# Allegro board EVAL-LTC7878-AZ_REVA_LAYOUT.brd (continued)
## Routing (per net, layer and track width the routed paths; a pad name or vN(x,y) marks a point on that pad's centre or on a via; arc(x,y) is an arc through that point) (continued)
UNNAMED_2_ADLTC7878_I88_VIN: length 3.5
  TOP w0.254: U1.2 73.02,90.91 72.01,91.92 C12.1
UNNAMED_2_ADLTC7878_I88_VOUT: length 27.7
  TOP w0.254: U1.25 77.95,92.43 78.74,93.22 78.74,93.73 v3(79.38,94.36) 79.95,94.36 R71.1 ; TP12.1 v4(59.31,88.65)
  LAYER_3 w0.254: v4(59.31,88.65) 64.14,88.65 65.41,89.92 68.58,89.92 69.85,88.65 72.01,88.65 75.06,91.69 76.58,91.69 79.25,94.36 v3(79.38,94.36)
UNNAMED_2_CAP_I49_N1: length 3.6
  TOP w0.254: U1.29 75.95,92.93 75.44,93.45 75.44,94.36 v4(75.18,94.61) 75.18,94.94 C17.1
  BOTTOM w0.254: v4(75.18,94.61) 75.18,94.94 C17.1
UNNAMED_2_CAP_I49_N2: length 6.1
  TOP w0.254: 76.28,94.98 C18.1 76.45,93.68 U1.28 ; 76.28,94.98 76.38,94.87 v4(76.71,94.87) ; 76.28,94.98 C17.2 76.26,96.03 R19.2 R13.2
  BOTTOM w0.254: C17.2 76.38,94.87 v4(76.71,94.87)
UNNAMED_2_CAP_I57_N1: length 1
  TOP w0.254: R12.2 C15.1
UNNAMED_2_CAP_I58_N1: length 1.9
  TOP w0.254: U1.31 74.95,92.55 74.17,93.33 74.17,93.54 C16.1
UNNAMED_2_CAP_I59_N2: length 2.6
  TOP w0.254: C19.2 73.48,85.29 74.95,86.76 U1.10
UNNAMED_2_CAP_I188_N1: length 26.9
  TOP w0.254: v3(80.52,95.5) 80.45,95.43 R71.2 ; R33.1 108.16,105.84 109.29,105.84 109.47,105.66 109.47,101.85 109.22,101.6 R31.2
  LAYER_5 w0.254: v3(98.3,101.6) 94.87,101.6 91.19,97.92 82.3,97.92 80.52,96.14 v3(80.52,95.5)
  vias: v1(96.14,108.71) v1(96.14,107.44) v1(96.14,106.17) v1(96.14,104.9) v1(97.41,108.71) v1(97.41,107.44) v1(97.41,106.17) v1(97.41,104.9) v1(98.68,108.71) v1(98.68,107.44) v1(98.68,106.17) v1(98.68,104.9) v1(99.95,108.71) v1(99.95,107.44) v1(99.95,106.17) v1(99.95,104.9) v3(95,103.76) v3(95.5,103.76) v3(96.01,103.76) v3(97.79,103.76) v3(98.3,103.76) v3(98.81,103.76) v3(101.09,103.76) v3(101.6,103.76) v3(102.11,103.76) v3(104.01,113.79) v3(104.01,112.27) v3(104.01,110.74) v3(104.39,103.76) v3(104.9,103.76) v3(105.41,103.76) v3(106.81,113.79) v3(106.81,112.27) v3(106.81,110.74)
UNNAMED_2_IND_I44_N1: length 38.5
  TOP w0.254: v3(74.04,107.44) 74.02,107.47 L1.1 ; R16.1 v3(77.47,97.92) ; R14.2 v3(63.5,105.28) ; R19.1 v3(76.2,97.79)
  LAYER_5 w0.254: v3(63.5,105.28) 63.12,104.9 63.12,100.08 63.88,99.31 73.79,99.31 75.18,97.92 75.18,97.54 75.82,96.9 76.83,96.9 77.47,97.54 v3(77.47,97.92) ; v3(76.2,97.79) 76.2,98.3 77.22,99.31 77.22,99.82 75.95,101.09 75.95,105.54 v3(74.04,107.44)
  vias: v2(70.36,104.39) v2(70.36,103.63) v2(71.12,104.39) v2(71.12,103.63) v2(71.88,104.39) v2(71.88,103.63) v2(72.64,104.39) v2(72.64,103.63) v2(73.41,104.39) v2(73.41,103.63)
UNNAMED_2_NCTESTPAD_I129_N1: length 5.2
  TOP w0.254: R34.2 R35.1
  TOP w0.381: R34.2 83.44,85.67 83.44,85.03 85.09,83.38 TP20.1
UNNAMED_2_RES_I34_N1: length 7.8
  TOP w0.254: v3(52.83,103.25) 52.83,103.61 M2.4
  LAYER_5 w0.508: v3(52.83,108.84) v3(52.83,103.25)
  BOTTOM w0.254: M6.4 52.29,108.3 v3(52.83,108.84)
UNNAMED_2_RES_I154_N1: length 7.7
  TOP w0.254: v3(58.93,110.49) 58.54,110.1 M1.4
  LAYER_5 w0.508: v3(53.34,110.49) v3(58.93,110.49)
  BOTTOM w0.254: M5.4 53.73,110.1 v3(53.34,110.49)
UNNAMED_2_TRANNMOSFET8P_I163_G: length 7.9
  TOP w0.254: v3(92.96,102.62) 92.67,102.91 M3.4
  LAYER_5 w0.508: v3(87.25,102.62) v3(92.96,102.62)
  BOTTOM w0.254: v3(87.25,102.62) 87.54,102.91 M7.4
UNNAMED_2_TRANNMOSFET8P_I168_G: length 8.2
  TOP w0.254: M4.4 94.12,104.55 93.73,104.15 v3(93.73,104.01)
  LAYER_5 w0.508: v3(93.73,109.86) v3(93.73,104.01)
  BOTTOM w0.254: M8.4 94.12,109.46 v3(93.73,109.86)
VFB_1: length 21.8
  TOP w0.254: v4(80.45,84.84) R36.1 R35.2 80.26,85.85 79.5,86.61 78.23,86.61 77.95,86.9 U1.16
  TOP w0.381: R5.1 TP18.1 v4(86.49,75.31)
  LAYER_5 w0.254: v4(80.45,84.84) 86.49,78.8 v4(86.49,75.31)
VFB_2: length 109.5
  TOP w0.254: U2.16 77.95,20.92 78.36,20.51 79.57,20.51 80.26,19.81 R65.2 R66.1 v4(80.45,18.8) ; TP43.1 v4(86.49,9.27)
  TOP w0.381: R5.2 v4(86.49,69.22)
  LAYER_4 w0.254: v4(86.49,9.27) 94.23,9.27 111.25,26.29 111.25,54.99 98.17,68.07 87.63,68.07 v4(86.49,69.22)
  LAYER_5 w0.254: v4(86.49,9.27) 86.49,12.76 v4(80.45,18.8)
VOUT: length 101.2
  TOP w0.254: TP19.1 v3(88.77,82.04) ; R32.2 110.24,101.56 109.98,101.81 109.98,105.66 110.14,105.82 R33.2 ; R63.2 110.14,39.78 109.98,39.62 109.98,35.77 R62.2
  TOP w0.381: R34.1 84.96,85.85 TP19.1 ; v3(88.77,16) TP44.1 84.96,19.81 R64.1
  LAYER_2 w0.381: v2(114.3,103.5) 114.3,95.63 100.71,82.04 v3(88.77,82.04) ; v3(88.77,16) 100.58,16 114.3,29.72 v2(114.3,37.47)
  vias: v2(114.3,108.58) v2(114.3,107.31) v2(114.3,106.05) v2(114.3,104.78) v2(114.3,42.55) v2(114.3,41.27) v2(114.3,40.01) v2(114.3,38.73) v2(115.19,108.58) v2(115.19,107.31) v2(115.19,106.05) v2(115.19,104.78) v2(115.19,103.5) v2(115.19,42.55) v2(115.19,41.27) v2(115.19,40.01) v2(115.19,38.73) v2(115.19,37.47) v3(115.44,113.92) v3(115.44,112.39) v3(115.44,110.87) v3(115.44,47.88) v3(115.44,46.35) v3(115.44,44.83) v3(118.24,113.92) v3(118.24,112.39) v3(118.24,110.87) v3(118.24,47.88) v3(118.24,46.35) v3(118.24,44.83)

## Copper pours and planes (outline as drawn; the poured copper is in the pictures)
SGND1 on LAYER_4 (solid shape): 74.04,87.63 72.96,87.63 72.71,87.38 72.39,87.38 72.39,87.69 72.83,88.14 74.04,88.14
SGND1 on TOP: 83.06,89.28 83.06,88.52 82.42,88.52 82.42,86.49 81.66,86.49 81.66,89.28
SGND1 on TOP: 79.12,82.55 78.36,82.55 78.36,84.45 79.12,84.45
SGND1 on TOP: 81.66,85.22 82.93,85.22 82.93,84.45 82.42,84.45 82.42,81.92 81.66,81.92
SGND1 on TOP: 83.06,91.31 83.06,90.55 81.66,90.55 81.66,91.31
SGND1 on TOP: 69.6,85.85 69.6,84.96 71.37,84.96 71.37,85.85
SGND1 on TOP: 80.99,82.55 82.84,82.55
SGND1 on BOTTOM: 68.58,92.08 68.58,82.04 83.82,82.04 83.82,92.08
SGND1 on LAYER_2: 38.1,135.79 39.27,134.62 39.26,134.49 39.24,134.37 39.24,101.35 57.53,83.06 67.82,83.06 68.58,83.82 68.58,88.9 69.98,88.9 69.98,92.08 83.82,92.08 83.82,81.92 69.72,81.92 68.58,80.77 56.64,80.77 36.96,100.46 36.96,134.37 36.94,134.49 36.93,134.62
SGND1 on LAYER_4: 79.38,87.63 73.41,87.63 73.41,91.82 79.38,91.82
SGND1 on LAYER_5: 73.41,91.82 73.41,88.52 74.8,88.52 75.56,87.76 79.38,87.76 79.38,91.82
SGND2 on TOP: 78.36,18.36 78.37,18.4 78.41,18.41 79.07,18.41 79.11,18.4 79.12,18.36 79.12,16.56 79.11,16.53 79.07,16.51 78.41,16.51 78.37,16.53 78.36,16.56
SGND2 on BOTTOM: 68.71,26.16 68.71,16.51 83.95,16.51 83.95,26.16
SGND2 on LAYER_2: 69.98,26.16 83.95,26.16 83.95,16.51 71.88,16.51 69.09,13.72 48.39,13.72 39.02,4.35 39.02,4.35 38.61,4.03 38.1,3.91 37.27,4.25 36.93,5.08 37.04,5.57 37.34,5.97 47.37,16 67.44,16 68.71,17.27 68.71,22.73 69.98,22.73
SGND2 on LAYER_4: 73.15,25.65 73.15,21.59 79.25,21.59 79.25,25.65
SGND2 on LAYER_5: 73.15,25.65 73.15,22.48 74.93,22.48 75.82,21.59 79.25,21.59 79.25,25.65
VIN on TOP: 2.79,129.79 58.8,129.79 58.8,111.25 18.92,111.25 18.41,110.74 18.41,81.28 36.2,63.5 58.93,63.5 58.93,45.09 16.51,45.09 16.26,45.34 16.26,60.58 2.54,74.3 2.54,129.54
VIN on BOTTOM: 2.92,129.79 58.93,129.79 58.93,111.12 18.92,111.12 18.41,110.62 18.41,81.28 36.2,63.5 58.93,63.5 58.93,45.09 16.51,45.09 16.26,45.34 16.26,60.58 2.54,74.3 2.54,129.41
DRVCC_1 on TOP: 70.61,94.36 69.22,94.36 69.22,95.38 70.61,95.38
DRVCC_1 on TOP: 57.62,92.46 59.47,92.46
DRVCC_1 on TOP: 70.48,90.74 70.48,90.11 71.95,90.11 72.14,90.3 72.14,90.49 71.88,90.74
DRVCC_2 on TOP: 70.74,28.19 69.22,28.19 69.22,29.34 70.74,29.34
GROUND on TOP (solid shape): 74.93,87.96 74.49,87.96 74.18,88.27 72.78,88.27 72.78,88.47 72.87,88.56 74.18,88.56 74.5,88.87 74.93,88.87
GROUND on TOP (solid shape): 74.93,21.92 74.5,21.92 74.19,22.23 72.81,22.22 72.81,22.4 72.92,22.52 74.19,22.52 74.5,22.82 74.93,22.82
GROUND on TOP, BOTTOM: 1.27,138.43 151.13,138.43 151.13,1.27 1.27,1.27
GROUND on LAYER_2: 1.27,138.43 151.13,138.43 151.13,1.27 1.27,1.27
GROUND on LAYER_3, LAYER_4: 1.27,1.27 1.27,138.43 151.13,138.43 151.13,1.27
GROUND on LAYER_5: 1.27,138.43 1.27,1.27 151.13,1.27 151.13,138.43 ; 1 cut-out
INTVCC_1 on TOP: 76.07,83.57 74.93,83.57 74.93,84.45 76.07,84.45
INTVCC_1 on TOP: 57.5,83.82 59.34,83.82
INTVCC_1 on TOP: 84.84,88.27 84.84,86.55 83.95,86.55 83.95,88.27
ITH_1 on TOP: 79.85,74.68 81.7,74.68
ITH_1 on TOP: 78.11,82.55 77.34,82.55 77.34,84.45 78.11,84.45
ITH_2 on TOP: 79.85,8.64 81.7,8.64
RUN_1 on TOP: 67.06,87 67.06,86.11 71.37,86.11 71.37,87
RUN_2 on TOP: 67.69,20.95 67.69,20.07 71.37,20.07 71.37,20.95
SS_1 on TOP: 74.13,74.68 75.98,74.68
SS_2 on TOP: 74.13,8.64 75.98,8.64
SYNC_2 on TOP: 83.06,90.3 83.06,89.53 81.66,89.53 81.66,90.3
UNNAMED_1_ADLTC7878_I123_BG1 on TOP: 51.82,35.94 51.82,34.67 52.83,34.67 52.83,35.94
UNNAMED_1_ADLTC7878_I123_BOOST1 on TOP: 71.88,29.34 72.83,29.34 72.83,28.57 73.47,27.94 74.42,27.94 74.42,26.92 73.41,26.92 71.88,28.45
UNNAMED_1_ADLTC7878_I123_BOOST2 on TOP: 73.79,19.56 73.79,18.03 74.04,18.03 74.04,17.32 74.03,17.29 73.99,17.27 73.08,17.27 73.04,17.29 73.03,17.32 73.03,19.56
UNNAMED_1_ADLTC7878_I123_CSN on TOP: 109.6,32.64 109.6,30.1 107.95,30.1 107.95,32.64
UNNAMED_1_ADLTC7878_I123_CSP on TOP: 109.6,34.8 109.6,32.89 107.19,32.89 107.19,34.8
UNNAMED_1_ADLTC7878_I123_EXTVCC on TOP: 71.38,23.75 71.95,23.75 71.95,23.63 71.4,23.07 71.33,22.99 71.29,22.91 71.28,22.9 71.26,22.87 71.25,22.86 71.25,22.84 71.25,22.71 71.25,22.29 69.85,22.29 69.85,23.67 69.86,23.71 69.9,23.72 71.24,23.72 71.31,23.73
UNNAMED_1_ADLTC7878_I123_FREQ on TOP: 80.26,23.19 80.28,23.23 80.31,23.24 81.36,23.24 81.39,23.23 81.41,23.19 81.41,22.53 81.39,22.49 81.36,22.48 80.31,22.48 80.28,22.49 80.26,22.53
UNNAMED_1_ADLTC7878_I123_ISNSD on TOP: 75.69,29.34 75.69,28.07 75.31,28.07 74.8,28.57 74.8,29.34
UNNAMED_1_ADLTC7878_I123_ISNSD on BOTTOM: 74.8,29.34 74.8,27.56 75.69,27.56 75.69,29.34
UNNAMED_1_ADLTC7878_I123_ISNSN on TOP: 77.28,27.43 77.28,29.02 77.15,29.15 77.15,30.1 79.38,30.1 79.38,29.02 78.49,29.02 78.49,27.43 78.36,27.3 77.41,27.3
UNNAMED_1_ADLTC7878_I123_ISNSN on BOTTOM: 77.72,28.32 75.95,28.32 75.95,27.56 77.72,27.56
UNNAMED_1_ADLTC7878_I123_ISNSP on TOP: 74.93,30.48 74.93,29.59 75.95,29.59 75.95,27.3 77.03,27.3 77.03,28.89 76.83,29.08 76.83,30.48
UNNAMED_1_ADLTC7878_I123_ITHB on TOP: 77.34,19.76 77.36,19.8 77.39,19.81 77.67,19.81 77.69,19.81 77.71,19.8 78.09,19.41 78.1,19.4 78.11,19.38 78.11,18.72 78.09,18.68 78.05,18.67 77.39,18.67 77.36,18.68 77.34,18.72
UNNAMED_1_ADLTC7878_I123_PGOOD on TOP: 68.42,8.64 70.27,8.64
UNNAMED_1_ADLTC7878_I123_SW1 on TOP: 62.48,34.67 62.48,43.56 59.56,43.56 59.05,43.05 57.28,43.05 57.28,44.83 53.34,44.83 53.34,34.67
UNNAMED_1_ADLTC7878_I123_SW1 on TOP: 74.42,29.21 74.42,28.32 73.53,28.32 73.15,28.7 73.15,29.21
UNNAMED_1_ADLTC7878_I123_SW1 on BOTTOM: 62.48,43.56 62.48,34.67 53.47,34.67 53.47,43.05 54.99,43.05 54.99,44.83 58.55,44.83 59.82,43.56
UNNAMED_1_ADLTC7878_I123_SW2 on TOP: 76.96,46.23 76.96,34.67 85.6,34.67 85.6,37.97 92.84,37.97 92.84,39.5 94.87,39.5 94.87,43.18 92.84,43.18 92.84,46.23
UNNAMED_1_ADLTC7878_I123_SW2 on TOP: 75.06,19.81 75.06,18.41 74.17,18.41 74.17,19.3 74.68,19.81
UNNAMED_1_ADLTC7878_I123_SW2 on TOP: 79.25,30.61 79.25,32.13 78.49,32.13 78.49,30.61
UNNAMED_1_ADLTC7878_I123_SW2 on BOTTOM: 77.09,46.23 77.09,34.67 86.61,34.67 86.61,37.97 92.96,37.97 93.34,38.35 95,38.35 95,42.04 92.96,42.04 92.96,46.23
UNNAMED_1_ADLTC7878_I123_VIN on TOP: 70.74,27.81 70.74,27.43 72.27,25.9 72.28,25.88 72.45,25.59 72.74,25.42 72.76,25.41 72.94,25.23 72.98,25.13 73.04,25.04 73.05,25.03 73.05,25 73,24.91 72.98,24.89 72.96,24.88 72.3,24.88 72.28,24.88 72.26,24.9 72.02,25.13 72.01,25.14 71.99,25.15 70.03,25.15 69.99,25.16 69.98,25.2 69.98,27.81
UNNAMED_1_ADLTC7878_I123_VOUT on TOP: 61.34,23.05 61.34,22.1 58.42,22.1 58.42,23.05
UNNAMED_1_ADLTC7878_I123_VOUT on TOP: 57.62,22.61 59.47,22.61
UNNAMED_1_ADLTC7878_I123_VOUT on TOP: 80.45,27.94 80.45,28.7 79.06,28.7 79.06,27.94
UNNAMED_1_CAP_I88_N2 on TOP: 109.86,34.8 110.74,34.8 110.74,32.64 111.51,32.64 111.51,30.1 109.86,30.1
UNNAMED_1_CAP_I107_N1 on TOP: 80.84,29.02 80.84,30.04 79.69,30.04 79.69,29.02
UNNAMED_1_CAP_I107_N1 on TOP: 95.25,49.4 95.25,38.48 94.11,37.34 93.34,37.34 93.34,35.56 93.73,35.18 108.46,35.18 108.46,36.2 109.09,36.2 109.09,40.13 109.47,40.13 109.47,49.4
UNNAMED_1_CAP_I107_N1 on BOTTOM: 95.25,49.53 95.25,38.61 94.36,37.72 93.34,37.72 93.34,35.81 93.85,35.31 108.97,35.31 108.97,49.53
UNNAMED_1_IND_I80_N1 on TOP: 77.98,30.61 77.98,32.13 77.22,32.13 77.22,30.61
UNNAMED_1_IND_I80_N1 on TOP: 63.25,46.23 63.25,34.67 75.44,34.67 75.44,46.23
UNNAMED_1_IND_I80_N1 on BOTTOM: 63.25,46.23 63.25,34.67 75.06,34.67 75.06,46.23
UNNAMED_1_RES_I60_N1 on TOP: 57.66,44.83 57.66,43.43 58.93,43.43 59.44,43.94 59.94,43.94 59.94,44.83
UNNAMED_1_RES_I60_N1 on BOTTOM: 54.61,44.83 54.61,43.43 53.09,43.43 53.09,44.83
UNNAMED_1_RES_I61_N1 on TOP: 51.69,36.2 53.09,36.2 53.09,38.48 51.69,38.48
UNNAMED_1_RES_I61_N1 on BOTTOM: 52.7,43.05 52.07,42.42 51.69,42.42 51.69,41.53 53.09,41.53 53.09,43.05
UNNAMED_1_RES_I75_N1 on TOP: 86.11,37.47 86.11,36.2 87.5,36.2 87.5,37.47
UNNAMED_1_RES_I75_N1 on TOP: 91.57,36.2 93.09,36.2 93.09,37.21 92.84,37.47 91.57,37.47
UNNAMED_1_RES_I75_N1 on BOTTOM: 88.65,37.47 88.65,36.2 87,36.2 87,37.47
UNNAMED_1_RES_I102_N1 on TOP: 93.47,39.24 93.47,37.72 93.98,37.72 94.87,38.61 94.87,39.24
UNNAMED_1_RES_I102_N1 on BOTTOM: 94.74,42.42 94.74,43.69 94.36,43.69 93.98,44.07 93.47,44.07 93.47,42.42
UNNAMED_2_ADLTC7878_I88_BG1 on TOP: 51.82,101.98 51.82,100.71 52.83,100.71 52.83,101.98
UNNAMED_2_ADLTC7878_I88_CSN on TOP: 109.6,98.68 109.6,96.14 107.95,96.14 107.95,98.68
UNNAMED_2_ADLTC7878_I88_CSP on TOP: 109.6,100.71 109.6,98.93 107.19,98.93 107.19,100.71
UNNAMED_2_ADLTC7878_I88_EXTVCC on TOP: 69.85,88.27 69.85,89.79 71.88,89.79 71.88,89.53 71.25,88.9 71.25,88.27
UNNAMED_2_ADLTC7878_I88_ISNSN on TOP: 77.15,93.6 77.15,95.06 76.96,95.25 76.96,96.14 79.25,96.14 79.25,95.12 78.36,95.12 78.36,93.47 78.23,93.34 77.41,93.34
UNNAMED_2_ADLTC7878_I88_ISNSN on BOTTOM: 75.82,94.36 75.82,93.6 77.53,93.6 77.53,94.36
UNNAMED_2_ADLTC7878_I88_PGOOD on TOP: 68.42,74.68 70.27,74.68
UNNAMED_2_ADLTC7878_I88_SW1 on TOP: 62.48,100.71 62.48,109.6 59.56,109.6 59.05,109.09 57.28,109.09 57.28,110.87 53.34,110.87 53.34,100.71
UNNAMED_2_ADLTC7878_I88_SW1 on TOP: 73.15,95.25 74.55,95.25 74.55,94.23 73.66,94.23 73.15,94.74
UNNAMED_2_ADLTC7878_I88_SW1 on TOP: 74.3,97.03 74.3,97.66 75.5,97.66 75.5,96.77 74.55,96.77
UNNAMED_2_ADLTC7878_I88_SW1 on BOTTOM: 62.48,109.6 62.48,100.71 53.47,100.71 53.47,109.09 54.99,109.09 54.99,110.87 58.55,110.87 59.82,109.6
UNNAMED_2_ADLTC7878_I88_SW2 on TOP: 77.09,112.27 77.09,100.71 85.72,100.71 85.72,104.01 92.96,104.01 92.96,105.54 95,105.54 95,109.22 92.96,109.22 92.96,112.27
UNNAMED_2_ADLTC7878_I88_SW2 on TOP: 74.17,85.85 75.06,85.85 75.06,84.45 74.17,84.45
UNNAMED_2_ADLTC7878_I88_SW2 on TOP: 78.36,96.65 78.36,98.17 79.12,98.17 79.12,96.65
UNNAMED_2_ADLTC7878_I88_SW2 on BOTTOM: 77.09,112.27 77.09,100.71 86.61,100.71 86.61,104.01 92.96,104.01 93.34,104.39 95,104.39 95,108.08 92.96,108.08 92.96,112.27
UNNAMED_2_ADLTC7878_I88_VIN on TOP: 69.98,93.85 69.98,91.19 72.01,91.19 72.39,90.81 73.53,90.81 73.53,91.19 73.03,91.19 70.74,93.47 70.74,93.85
UNNAMED_2_ADLTC7878_I88_VOUT on TOP: 61.47,89.03 61.47,88.01 58.29,88.01 58.29,89.03
UNNAMED_2_ADLTC7878_I88_VOUT on TOP: 57.62,88.65 59.47,88.65
UNNAMED_2_ADLTC7878_I88_VOUT on TOP: 80.39,94.74 80.39,93.85 78.87,93.85 78.87,94.74
UNNAMED_2_CAP_I49_N1 on BOTTOM: 74.68,95.38 74.68,93.6 75.56,93.6 75.56,95.38
UNNAMED_2_CAP_I49_N2 on TOP: 75.82,93.34 75.82,95.63 74.8,95.63 74.8,96.52 76.71,96.52 76.71,95.12 76.9,94.93 76.9,93.34
UNNAMED_2_CAP_I57_N1 on TOP: 79.12,82.3 79.12,81.41 77.34,81.41 77.34,82.3
UNNAMED_2_CAP_I58_N1 on TOP: 71.88,95.38 72.83,95.38 72.83,94.55 73.41,93.98 74.42,93.98 74.42,93.09 73.28,93.09 71.88,94.49
UNNAMED_2_CAP_I59_N2 on TOP: 73.03,85.6 73.03,83.31 74.04,83.31 74.04,84.07 73.91,84.2 73.91,85.6
UNNAMED_2_CAP_I132_N2 on TOP: 109.86,100.71 110.74,100.71 110.74,98.68 111.51,98.68 111.51,96.14 109.86,96.14
UNNAMED_2_CAP_I188_N1 on TOP: 79.63,95.89 79.63,95 80.77,95 80.77,95.89
UNNAMED_2_CAP_I188_N1 on TOP: 95.38,115.57 95.38,104.65 94.23,103.5 93.47,103.5 93.47,101.73 93.85,101.35 108.58,101.35 108.58,102.23 109.09,102.23 109.09,106.3 109.47,106.3 109.47,115.57
UNNAMED_2_CAP_I188_N1 on BOTTOM: 95.38,115.57 95.38,104.65 94.49,103.76 93.47,103.76 93.47,101.85 93.98,101.35 109.09,101.35 109.09,115.57
UNNAMED_2_IND_I44_N1 on TOP: 77.09,96.65 77.09,98.17 77.85,98.17 77.85,96.65
UNNAMED_2_IND_I44_N1 on TOP, BOTTOM: 63.25,112.27 63.25,100.71 75.44,100.71 75.44,112.27
UNNAMED_2_NCTESTPAD_I129_N1 on TOP: 84.17,82.55 86.01,82.55
UNNAMED_2_NCTESTPAD_I129_N1 on TOP: 83.63,86.23 83.63,85.47 81.66,85.47 81.66,86.23
UNNAMED_2_RES_I34_N1 on TOP: 51.69,102.23 53.09,102.23 53.09,104.52 51.69,104.52
UNNAMED_2_RES_I34_N1 on BOTTOM: 52.7,109.09 52.07,108.46 51.69,108.46 51.69,107.57 53.09,107.57 53.09,109.09
UNNAMED_2_RES_I154_N1 on TOP: 57.66,110.87 57.66,109.47 58.93,109.47 59.44,109.98 59.94,109.98 59.94,110.87
UNNAMED_2_RES_I154_N1 on BOTTOM: 54.61,110.87 54.61,109.47 53.09,109.47 53.09,110.87
UNNAMED_2_TRANNMOSFET8P_I163_G on TOP: 91.69,102.36 93.22,102.36 93.22,103.38 92.96,103.63 91.69,103.63
UNNAMED_2_TRANNMOSFET8P_I163_G on TOP: 86.11,103.5 86.11,102.23 87.5,102.23 87.5,103.5
UNNAMED_2_TRANNMOSFET8P_I163_G on BOTTOM: 88.65,103.5 88.65,102.23 87,102.23 87,103.5
UNNAMED_2_TRANNMOSFET8P_I168_G on TOP: 93.47,105.28 93.47,103.76 93.98,103.76 94.87,104.65 94.87,105.28
UNNAMED_2_TRANNMOSFET8P_I168_G on BOTTOM: 94.87,108.46 94.87,109.86 94.23,109.86 93.98,110.11 93.47,110.11 93.47,108.46
VFB_1 on TOP: 81.41,86.23 81.41,84.45 80.26,84.45 80.26,85.98 80.52,86.23
VFB_1 on TOP: 85.56,74.68 87.41,74.68
VFB_2 on TOP: 85.56,8.64 87.41,8.64
VOUT on TOP: 87.29,82.55 89.24,82.55
VOUT on TOP: 109.98,115.57 135.89,115.57 135.89,93.98 149.86,93.98 149.86,67.31 135.89,67.31 135.89,36.2 110.36,36.2 110.36,40.13 109.98,40.13 109.98,49.4 121.28,49.4 121.28,102.23 110.36,102.23 110.36,106.3 109.98,106.3
VOUT on BOTTOM: 113.03,115.57 135.89,115.57 135.89,93.98 149.86,93.98 149.86,67.31 135.89,67.31 135.89,36.2 112.39,36.2 112.39,49.4 121.28,49.4 121.28,102.23 113.03,102.23

Small or netless copper shapes (teardrops, artwork), in the pictures only: 87 on TOP, 2 on BOTTOM, 2 on LAYER_2, 2 on LAYER_3, 6 on LAYER_4, 41 on LAYER_5

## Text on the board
Ref Des/Silkscreen Top: 70V PARALLEL DUAL PHASE | 4-SWITCH BUCK-BOOST | EVAL-LTC7878-AZ | LTC7878
DIMENSION: FAB NOTES REVISION: 2ND NOVEMBER 2022 | 8.   IMPEDANCE REQUIREMENTS: IF NO STACKUP IS DEFINED, THE VENDOR IS ALLOWED TO ADJUST THE DIELECTRIC | 13.  PLATING SPECIFICATION: | 9.   FILLET OPTIONS TO ENHANCE RELIABILITY AT PAD JUNCTIONS WHERE SPACING PERMITS. | 10.  THIEVING: | 11.  LAYER TO LAYER REGISTRATION SHALL BE WITHIN 0.003 INCHES. | 12.  DRILL SIZES ARE FINISHED HOLE SIZES. ALL HOLES SHALL BE LOCATED WITHIN 0.005 INCHES DTP,UNLESS SPECIFIED. | 14.  SURFACE FINISH: | 15.  SOLDERMASK: | 1.   DIMENSIONS ARE IN INCHES (EXCEPT WHERE NOTED). | ALL DOCUMENTS & SPECIFICATIONS REFERRED TO BELOW SHOULD BE THE LATEST REVISIONS. | 2.  BOARD MATERIAL:(USE CHECKED ITEMS) | 3.   ALL LAMINATES & BONDING MATERIALS SHOULD BE SELECTED FROM IPC-4101 OR IPC-4103,(TG>170 DEGC TD>300 DEGC) | 4.   REFER TO IPC-6010 SERIES, CLASS 2 FOR FABRICATION. | 5.   REFER TO LAMINATION DIAGRAM FOR OVERALL BOARD THICKNESS, TOLERANCE APPLIES AFTER ALL LAMINATION AND PLATING | 6.   BOW & TWIST NOT TO EXCEED 0.0075 INCHES (0.75%) PER LINEAR INCH AND SHOULD BE MEASURED PER IPC-TM-650, METHOD 2.4.22. | 7.   ACCEPTABILITY PER ADI SPECIFICATION TST00115. | 16.  APPLY SILKSCREEN TO BOTH SIDES USING A NON-CONDUCTIVE, EPOXY BASED INK PER ARTWORK. | ( ) FILLETS ALLOWED | (X) FILLETS NOT ALLOWED | ( ) VENDOR MAY ADD THIEVING TO COMPENSATE FOR LOW COPPER DENSITY AREAS MAINTAINING A MINIMUM | (X) VENDOR MAY NOT ADD THIEVING TO COMPENSATE FOR LOW COPPER DENSITY AREAS. | (X) LPI | ( ) OTHER_________ | COLOR | ( ) GREEN | (X) OTHER_________ | ( ) WHITE | HINDER PROPER SOLDER WICKING. BARREL RELIEF ON SOLDERMASK ALLOWED IN UNFILLED VIA IN PAD HOLES. | (X) REFER TO LAMINATION DIAGRAM FOR FINISHED COPPER WEIGHT/THICKNESS REQUIRMENTS | (X) IMMERSION GOLD (ENIG) 1.58-3.94 MICRO INCHES OVER 118-236 MICRO INCHES MIN. OF ELECTROLESS NICKEL PER IPC-4552 | ( ) OSP (ORGANIC SOLDERABILITY PRESERVATIVE) | ( ) IMMERSION SILVER | ( ) SOFT WIRE BONDABLE GOLD 30-50 MICRO INCHES OF SOFT WIRE | ( ) EDGE CONNECTOR FINGERS ARE TO BE PLATED WITH 100 MICRO-INCHES(.0001") OF LOW STRESS | THICKNESS & TRACE WIDTHS TO MEET THE IMPEDANCE REQUIREMENT. IF SPECIFIED, THE VENDOR MUST | TRACE WIDTH & SPACING THAT IMPACT THE REQUIREMENTS MUST HAVE WRITTEN APPROVAL FROM ADI. | MINIMUM BARREL PLATING OF 0.001 INCHES. PLATED HOLES SHALL NOT BE ROUGH OR IRREGULAR SO AS TO | SOLDERMASK OVER BARE COPPER OR BARE GOLD (BOTH SIDES) TO MEET IPC-SM-840. | IF PRESENT,DO NOT MODIFY SOLDERMASK DEFINED PADS (MASK OPENINGS LESS THAN COPPER PAD) WITHOUT APPROVAL. | MEET THE REQUIREMENTS LISTED IN THE IMPEDANCE TABLE. ANY ADJUSTMENT MADE TO THE DEFINED STACKUP, | PROCESSES. FINISHED THICKNESS MEASURED FROM TOP COPPER TO BOTTOM COPPER. | (X)  ISOLA 370HR OR S1000-2 OR IT180 OR EQUIVALENT | ( )  ISOLA-FR408HR OR EQUIVALENT | ( )  ISOLA IS410 | ( )  MEGTRON 6 | ( )  NELCO-4000-13 | ( )  ROGERS 4350B | ( ) ROGERS 3003 | ( ) ARLON 85N | ( ) EM370D | ( )  OTHER ________________________ | UL FLAMMABILITY RATING 94V-0. BOARD MATERIAL & CONSTRUCTION SHALL MEET THE REQUIREMENTS OF UL796/UL796F. | BONDABLE GOLD OVER 100-150 MICRO INCHES OF NICKEL | NICKEL UNDER 30 MICRO-INCHES (.0003') OF GOLD | 0.100 INCH CLEARANCE FROM ALL COPPER FEATURES, | THE STARTING COPPER WEIGHT/THICKNESS CAN VARY AS LONG AS THE FINISHED COPPER | WEIGHT/THICKNESS IS NOT LESS THAN THE SPECIFIED VALUE. | UNLESS OTHERWISE SPECIFIED | WHITE | BLUE | HOMOGENOUS MATERIALS IN THIS BOARD SHALL BE COMPLAINT WITH THE EU DIRECTIVE 2002/95/EC | WORKMANSHIP SHALL CONFORM TO IPC-A-600, CLASS 2. | 21.  INTENTIONAL SHORTS: | 17.  FINAL ELECTRICAL TEST TO BE PERFORMED USING PROVIDED IPC-D-356A NETLIST OR ODB++ FORMAT FILE. | 22.  PEMNUTS: | 23.  MANUFACTURER TO ETCH/STAMP WITH PERMANENT NON-CONDUCTIVE INK | ON SECONDARY SIDE UNLESS OTHERWISE SPECIFIED: | 18.  A TIME DOMAIN REFLECTOMETER REPORT (TDR) FOR EACH IMPEDANCE CONTROLLED LAYER & A CERTIFICATE | 19.  IF PRESENT, ALL BLIND/BURIED VIAS WITH AN ASPECT RATIO <1:1 TO BE PLATED SHUT WITH COPPER WHEN | 20.  FOR VIA FILL INFORMATION REFER TO DRILL CHART: | 25. PANELIZATION: | 27.  MINIMUM DESIGN LINE WIDTH IS .006 INCH. | 28.  MINIMUM DESIGN LINE SPACING IS .006 INCH. | IS ACCEPTABLE, ALL OTHER INSTANCES MUST BE REPORTED. | IF AN INTENTIONAL SHORT REPORT IS SUPPLIED AND DOES NOT MATCH THE FAB DATA THEN | THE PCB SHALL HAVE A VERIFICATION STAMP. | (X)  NON-CONDUCTIVE EPOXY FILL ALL 0.012 INCHES DRILLED VIAS | ( )  COPPER FILL ALL 0.XXXX INCHES DRILLED VIAS | ( ) PEMNUTS TO BE INSTALLED BY FABRICATOR | ( ) PEMNUTS NOT TO BE INSTALLED BY FABRICATOR | (X) NOT APPLICABLE | USED AS VIA-IN-PAD OR AS A STACKED VIA. BLIND/BURIED VIAS WITH AN ASPECT RATIO >1:1 TO BE FILLED | A. UL CODE-FLAMMABILITY RATING FOR THOSE APPROVED MATERIALS(IF APPLICABLE) | B. DATE CODE | C. LOT NUMBER | D. MANUFACTURER LOGO | BOARDS TO BE SHIPPED IN ARRAY AND KEPT INTACT | PANEL TO BE SUBJECTED TO CUSTOMERS APPROVAL | PANEL SOLDER PASTE STENCIL GERBER TO BE PROVIDED TO ANALOG | CAN'T BE PERFORMED BECAUSE THE TRACE LENGTH IS TOO SHORT ON THE OUTER LAYERS AT THE PIN ESCAPES | ADI APPROVAL IS REQUIRED. | OF COMPLIANCE SHALL BE PROVIDED BY VENDOR AT TIME OF SHIPMENT. INSTANCES WHERE TDR TESTING | WITH NON-CONDUCTIVE EPOXY. | TOOLING: | FINISH: | NOTES: | MATERIAL: | TESTING: | MISCELLANEOUS: | "0" | SEE NOTE #20
User.17: 08-      -07 | L2 INTERNAL
User.18: 08-      -08 | L3 INTERNAL
User.24: IN | OUT | SUPPLY | POWER | V | I | LOAD | A | - | +
User.45: FIGURE | SIZE | 6.0 | 10.0 | 12.0 | 14.0 | 70.0 | 200.0 | 187.0 | PLATED | NON-PLATED | FINISHED HOLES IN MILS | ALL UNITS ARE IN MILS | QTY | 63 | 245 | 128 | 376 | 12 | 4 | TOLERANCE/NOTES
